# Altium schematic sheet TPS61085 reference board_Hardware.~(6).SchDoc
size 431 x 279 mm; Date: Not shown in title block; ApprovedBy: Not shown in title block; CheckedBy: Not shown in title block; Author: Not shown in title block; CompanyName: Not shown in title block; Engineer: Not shown in title block; Organization: Not shown in title block; Address1: Not shown in title block; Address2: Not shown in title block; Address3: Not shown in title block; Address4: Not shown in title block; DocumentNumber: 1; Revision: Use project parameter SCH_Rev; SheetNumber: 3; SheetTotal: 3; PageSetup: Record=PageOptions¦CenterHorizontal=True¦CenterVertical=True¦PrintScale=1.00¦XCorrection=1.00¦YCorrection=1.00¦PrintKind=0¦BorderSize=5000000¦LeftOffset=0¦BottomOffset=0¦Orientation=2¦PaperLength=1000¦PaperWidth=1000¦Scale=100¦PaperSource=15¦PrintQuality=600¦MediaType=1¦DitherType=10¦PaperKind=Letter¦PrintScaleMode=1
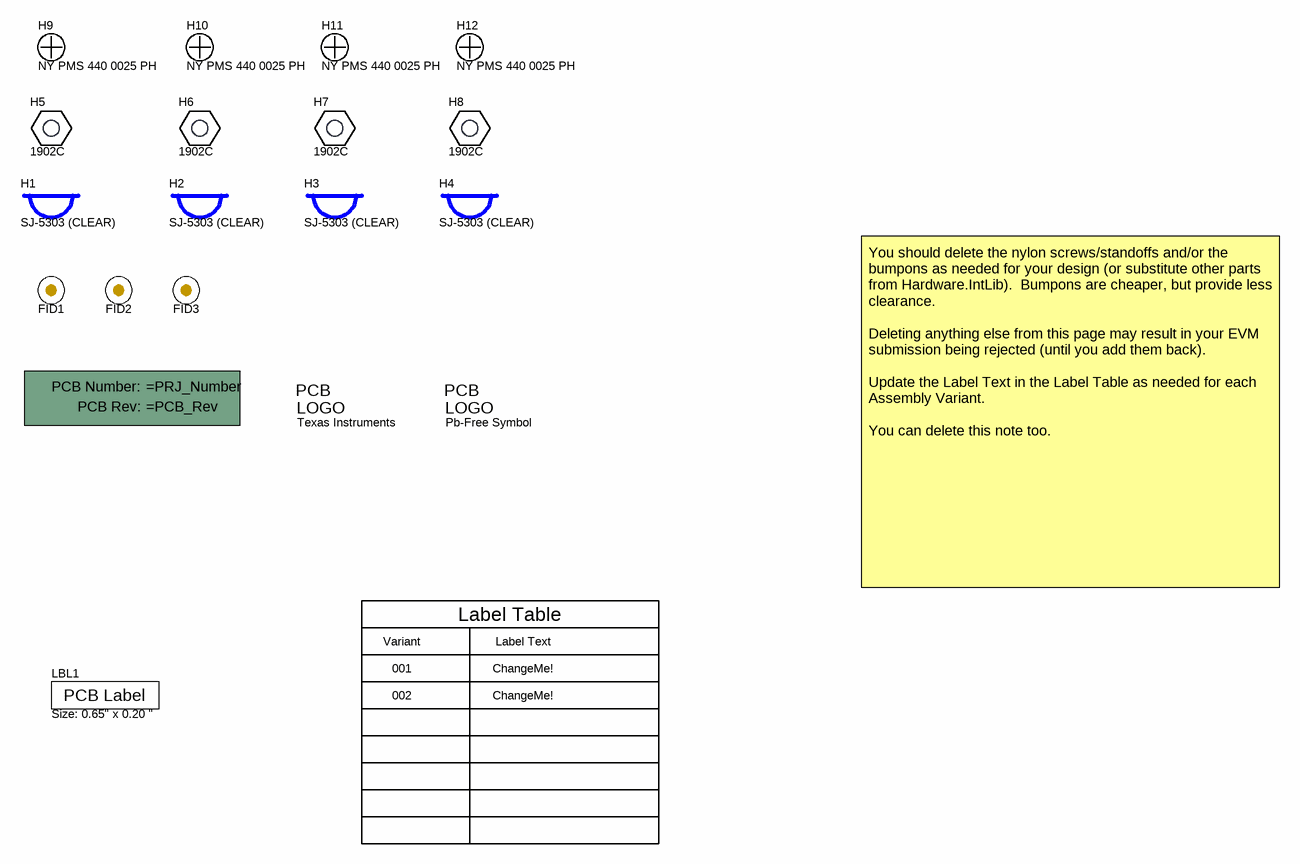
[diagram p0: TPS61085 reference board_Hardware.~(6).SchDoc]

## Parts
!PCB1  Printed Circuit Board  (value not drawn)  (mechanical)
FID1  Fiducial  [Fiducial10-20]  (value not drawn)
FID2  Fiducial  [Fiducial10-20]  (value not drawn)
FID3  Fiducial  [Fiducial10-20]  (value not drawn)
H1  SJ-5303 (CLEAR)  [Bumpon_SJ5003Transparent]
H2  SJ-5303 (CLEAR)  [Bumpon_SJ5003Transparent]
H3  SJ-5303 (CLEAR)  [Bumpon_SJ5003Transparent]
H4  SJ-5303 (CLEAR)  [Bumpon_SJ5003Transparent]
H5  1902C  [Keystone_1902C]
H6  1902C  [Keystone_1902C]
H7  1902C  [Keystone_1902C]
H8  1902C  [Keystone_1902C]
H9  NY PMS 440 0025 PH  [NY PMS 440 0025 PH]
H10  NY PMS 440 0025 PH  [NY PMS 440 0025 PH]
H11  NY PMS 440 0025 PH  [NY PMS 440 0025 PH]
H12  NY PMS 440 0025 PH  [NY PMS 440 0025 PH]
LBL1  Size: 0.65" x 0.20 "  [Label_650x200]
Logo1  Texas Instruments  [TI_Stacked_SolderMask_Small]  (no BOM)
Logo2  Pb-Free Symbol  [Pb-Free_Overlay_Small]  (no BOM)

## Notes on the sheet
- Variant
- Label Table
- Label Text
- You should delete the nylon screws/standoffs and/or the bumpons as needed for your design (or substitute other parts from Hardware.IntLib).  Bumpons are cheaper, but provide less clearance.
  Deleting anything else from this page may result in your EVM submission being rejected (until you add them back).
  Update the Label Text in the Label Table as needed for each Assembly Variant.
  You can delete this note too.
- 001
- 002
- ChangeMe!

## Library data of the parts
!PCB1 = PCB: Manufacturer: Any; SymbolCreator: a0412235
FID1-FID3 = Fiducial: Fiducial mark.  There is nothing to buy or mount.; SymbolCreator: codlsc
H1-H4 = SJ-5303 (CLEAR): Bumpon, Hemisphere, 0.44 X 0.20, Clear; Manufacturer: 3M; SymbolCreator: a0412235
H5-H8 = 1902C: Standoff, Hex, 0.5"L #4-40 Nylon; Manufacturer: Keystone; CompType: Hardware
H9-H12 = NY PMS 440 0025 PH: Machine Screw, Round, #4-40 x 1/4, Nylon, Philips panhead; Manufacturer: B&F Fastener Supply; CompType: Hardware; SymbolCreator: codlsc; U/M: EA
LBL1 = THT-14-423-10: Thermal Transfer Printable Labels, 0.650" W x 0.200" H - 10,000 per roll; Manufacturer: Brady; SymbolCreator: a0412235; CompType: Label
Logo1 = TI_Logo: Texas Instrument Corporate Signature; SymbolCreator: codlsc
Logo2 = Pb-Free: SymbolCreator: a0412235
